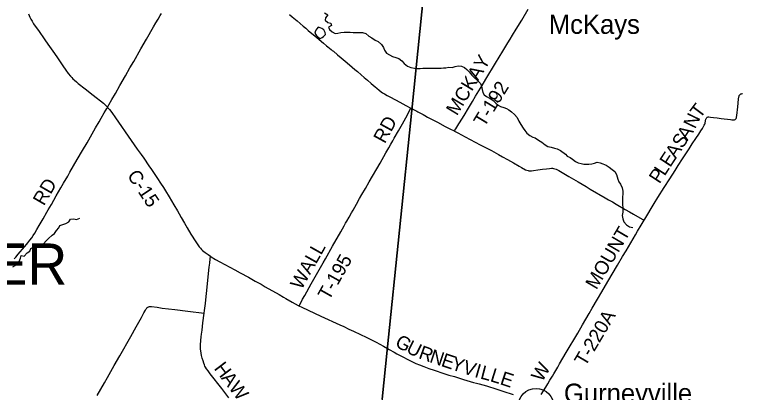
# Model space of a CAD drawing. Extents: x 1442749 to 1756758, y 235267 to 677782.
# Drawn here: x 1568709 to 1584541, y 554957 to 563182 of the extents above; entities that cross this region are included whole.
import ezdxf

# ---------------------------------------------------------------- set-up
doc = ezdxf.new("R2010")
doc.units = 0
for name, color, linetype in [('GM_X_County_Road', 7, 'Continuous'), ('GM_X_County_Road_Text', 7, 'Continuous'), ('GM_X_Minor_Lake', 7, 'Continuous'), ('GM_X_Minor_River', 7, 'Continuous'), ('GM_X_Township', 7, 'Continuous'), ('GM_X_Township_Road', 7, 'Continuous'), ('GM_X_Township_Road_Text', 7, 'Continuous'), ('GM_X_Township_Text', 7, 'Continuous'), ('GM_X_Unincorporated', 7, 'Continuous'), ('GM_X_Unincorporated_Text', 7, 'Continuous')]:
    doc.layers.add(name, color=color, linetype=linetype)

msp = doc.modelspace()

# ---------------------------------------------------------------- linework, layer by layer
at = {"layer": 'GM_X_County_Road'}
for points in [[(1569012, 563200), (1569044, 563125), (1569065, 563081), (1569090, 563035), (1569124, 562983), (1569159, 562932), (1569228, 562836), (1569370, 562631), (1569436, 562537), (1569505, 562437), (1569575, 562334), (1569640, 562240), (1569698, 562156), (1569761, 562064), (1569825, 561973), (1569878, 561902), (1569925, 561843), (1569952, 561811), (1569977, 561784), (1570010, 561753), (1570054, 561714), (1570092, 561683), (1570242, 561567), (1570418, 561430), (1570641, 561250), (1570678, 561218), (1570709, 561188), (1570733, 561162)], [(1570733, 561162), (1570761, 561214), (1570828, 561334), (1570903, 561465), (1571001, 561636), (1571122, 561850), (1571219, 562021), (1571301, 562163), (1571457, 562433), (1571579, 562643), (1571734, 562913), (1571784, 563002), (1571831, 563085), (1571878, 563164), (1571904, 563205)], [(1568701, 557862), (1568738, 557903), (1568790, 557967), (1568830, 558015), (1568934, 558137), (1568996, 558210), (1569045, 558271), (1569084, 558323), (1569117, 558372), (1569150, 558425), (1569194, 558501), (1569244, 558589), (1569330, 558737), (1569413, 558882), (1569443, 558933), (1569510, 559050), (1569618, 559237), (1569717, 559411), (1569777, 559513), (1569866, 559666), (1569914, 559748), (1570074, 560027), (1570188, 560226), (1570286, 560393), (1570472, 560714), (1570548, 560845), (1570596, 560930), (1570660, 561041), (1570695, 561101), (1570715, 561134), (1570728, 561154), (1570733, 561162)], [(1570733, 561162), (1570740, 561154), (1570771, 561116), (1570823, 561048), (1570907, 560931), (1571245, 560442), (1571378, 560255), (1571461, 560137), (1571519, 560053), (1571633, 559889), (1571687, 559810), (1571758, 559704), (1571818, 559614), (1571886, 559513), (1571951, 559415), (1571993, 559348), (1572074, 559216), (1572175, 559044), (1572253, 558911), (1572290, 558845), (1572334, 558768), (1572405, 558642), (1572462, 558543), (1572547, 558403), (1572652, 558236), (1572697, 558168), (1572726, 558128), (1572752, 558095), (1572773, 558070), (1572796, 558047), (1572823, 558024), (1572854, 558000), (1572919, 557956), (1572974, 557921)], [(1572974, 557921), (1572988, 557912), (1573083, 557854), (1573175, 557802), (1573286, 557740), (1573497, 557627), (1573615, 557562), (1573797, 557463), (1573946, 557381), (1574070, 557312), (1574163, 557258), (1574305, 557176), (1574396, 557124), (1574462, 557087), (1574562, 557031), (1574613, 557001), (1574748, 556920), (1574811, 556884), (1574877, 556849), (1574896, 556839)], [(1574896, 556839), (1574957, 556810), (1575374, 556618), (1575785, 556429), (1575871, 556389), (1575981, 556337), (1576080, 556292), (1576235, 556222), (1576356, 556163), (1576476, 556102), (1576572, 556050), (1576733, 555962), (1576860, 555892)], [(1576860, 555892), (1576966, 555834), (1577027, 555801)], [(1577027, 555801), (1577153, 555733), (1577261, 555677), (1577366, 555624), (1577437, 555590), (1577519, 555555), (1577613, 555519), (1577718, 555481), (1577833, 555442), (1578048, 555373), (1578158, 555337), (1578277, 555301), (1578474, 555239), (1578621, 555193), (1578690, 555173), (1578754, 555157), (1578817, 555142), (1578891, 555125), (1578977, 555103), (1579043, 555083), (1579137, 555054), (1579333, 554988), (1579554, 554914)]]:
    msp.add_lwpolyline(points, dxfattribs=at)
at = {"layer": 'GM_X_Minor_Lake'}
for points in [[(1575264, 562839), (1575254, 562826), (1575237, 562780), (1575271, 562734), (1575316, 562688), (1575359, 562662), (1575402, 562683), (1575430, 562706)], [(1575430, 562706), (1575473, 562748), (1575464, 562794), (1575439, 562846), (1575396, 562879), (1575354, 562896), (1575310, 562907), (1575285, 562868), (1575264, 562839)]]:
    msp.add_lwpolyline(points, dxfattribs=at)
at = {"layer": 'GM_X_Minor_River'}
for points in [[(1575453, 563219), (1575520, 563176), (1575473, 563112), (1575464, 563061), (1575521, 563011), (1575589, 562994), (1575600, 562942), (1575541, 562905), (1575562, 562854), (1575621, 562805), (1575686, 562773), (1575739, 562780), (1575809, 562791), (1575879, 562796), (1575950, 562800), (1576012, 562797), (1576072, 562792), (1576148, 562792), (1576222, 562791), (1576280, 562794), (1576350, 562766), (1576415, 562713), (1576478, 562673), (1576551, 562626), (1576617, 562594), (1576692, 562529), (1576737, 562466), (1576754, 562409), (1576798, 562342), (1576864, 562303), (1576933, 562267), (1576999, 562250), (1577065, 562229), (1577132, 562171), (1577181, 562116), (1577258, 562060), (1577332, 562033), (1577405, 562017), (1577467, 562006), (1577533, 562007), (1577592, 562012), (1577650, 562014), (1577700, 562015), (1577754, 562014), (1577810, 562013), (1577874, 562016), (1577925, 562015), (1577989, 562016), (1578039, 562019), (1578089, 562024), (1578154, 562037), (1578224, 562033), (1578292, 562050), (1578359, 562065), (1578431, 562061), (1578494, 562028), (1578549, 561983), (1578594, 561932), (1578653, 561860), (1578712, 561801), (1578781, 561745), (1578844, 561678), (1578867, 561625), (1578878, 561551), (1578892, 561484), (1578921, 561434), (1578973, 561397), (1579052, 561353), (1579117, 561310), (1579174, 561252), (1579226, 561209), (1579277, 561184), (1579353, 561159), (1579407, 561139), (1579458, 561108), (1579521, 561065), (1579584, 561008), (1579643, 560938), (1579680, 560859), (1579722, 560788), (1579769, 560711), (1579810, 560658)], [(1579227, 561268), (1579151, 561326), (1579152, 561325)], [(1579810, 560658), (1579853, 560597), (1579916, 560550), (1579984, 560516), (1580035, 560497), (1580107, 560450), (1580176, 560402), (1580247, 560343), (1580310, 560311), (1580380, 560296), (1580452, 560277), (1580508, 560257), (1580585, 560224), (1580689, 560141)], [(1580689, 560141), (1580727, 560097), (1580793, 560069), (1580845, 560037), (1580908, 559981), (1580970, 559958), (1581035, 559939), (1581091, 559928), (1581143, 559926), (1581203, 559925), (1581262, 559930), (1581324, 559945), (1581380, 559966), (1581450, 559957), (1581502, 559936), (1581576, 559907), (1581639, 559863), (1581710, 559810), (1581764, 559763), (1581801, 559703), (1581814, 559652), (1581829, 559596), (1581852, 559539), (1581891, 559489), (1581924, 559414), (1581943, 559337), (1581940, 559281), (1581930, 559207), (1581932, 559157), (1581930, 559093), (1581932, 559039), (1581937, 558983), (1581940, 558932), (1581939, 558880), (1581926, 558812), (1581942, 558734), (1581963, 558667), (1582016, 558606), (1582088, 558563), (1582155, 558546)], [(1568669, 557690), (1568724, 557717), (1568755, 557785), (1568808, 557810), (1568839, 557877), (1568850, 557935), (1568918, 557924), (1568982, 557993), (1569045, 558032), (1569062, 558087), (1569127, 558128), (1569193, 558145), (1569266, 558165), (1569337, 558194), (1569396, 558257), (1569449, 558308), (1569525, 558377), (1569576, 558414), (1569621, 558481), (1569670, 558538), (1569697, 558594), (1569758, 558613), (1569827, 558631), (1569889, 558672), (1569929, 558728), (1570001, 558736), (1570057, 558723), (1570128, 558748)]]:
    msp.add_lwpolyline(points, dxfattribs=at)
at = {"layer": 'GM_X_Township'}
for points in [[(1567480, 573618), (1572928, 573040), (1578513, 572449), (1578438, 571717), (1577745, 564960), (1577349, 561102), (1576814, 555881), (1576704, 554811), (1576386, 550844), (1576369, 550638), (1576189, 548397), (1576129, 547648), (1575922, 544864), (1575631, 540931), (1575571, 540239), (1575500, 539411), (1574568, 539459), (1566007, 539894)], [(1576704, 554811), (1576814, 555881), (1577349, 561102), (1577745, 564960), (1578438, 571717), (1578513, 572449), (1579838, 572308), (1580857, 572200), (1588468, 571492), (1591507, 571209), (1594558, 570925), (1600110, 570408), (1601218, 570299), (1605315, 569892), (1608125, 569657), (1616080, 568853), (1618534, 568633), (1622375, 568282), (1623453, 568184), (1622446, 566839), (1615321, 557320), (1613178, 554457)]]:
    msp.add_lwpolyline(points, dxfattribs=at)
at = {"layer": 'GM_X_Township_Road'}
for points in [[(1578277, 560645), (1578288, 560663), (1578306, 560692), (1578375, 560804), (1578450, 560928), (1578508, 561023), (1578559, 561107), (1578668, 561290), (1578738, 561405), (1578807, 561520), (1578878, 561638), (1578962, 561776), (1579170, 562121), (1579332, 562388), (1579441, 562567), (1579487, 562643), (1579539, 562730), (1579621, 562865), (1579741, 563061), (1579884, 563300)], [(1574688, 563185), (1574750, 563132), (1574855, 563043), (1574922, 562985), (1574985, 562932), (1575044, 562882), (1575099, 562835), (1575212, 562741), (1575275, 562689), (1575382, 562597), (1575430, 562557), (1575495, 562502), (1575523, 562479), (1575597, 562419), (1575620, 562400), (1575643, 562382), (1575733, 562305), (1575810, 562240), (1575941, 562130), (1576055, 562036), (1576110, 561989), (1576165, 561943), (1576250, 561871), (1576314, 561815), (1576384, 561755), (1576469, 561683), (1576550, 561612), (1576588, 561580), (1576639, 561538), (1576685, 561502), (1576715, 561481), (1576757, 561455), (1576817, 561421), (1576886, 561383), (1577087, 561278), (1577223, 561206), (1577330, 561148)], [(1582401, 558705), (1582416, 558729), (1582618, 559070), (1582698, 559202), (1582837, 559421), (1582959, 559607), (1583079, 559791), (1583146, 559896), (1583241, 560042), (1583337, 560191), (1583382, 560259), (1583451, 560367), (1583526, 560483), (1583591, 560581), (1583638, 560652), (1583669, 560699), (1583697, 560743), (1583712, 560773), (1583722, 560798), (1583728, 560820), (1583739, 560869), (1583748, 560905), (1583752, 560919), (1583757, 560930), (1583764, 560939), (1583772, 560945), (1583779, 560950), (1583784, 560952), (1583793, 560953), (1583809, 560954), (1583845, 560951), (1583910, 560944), (1583991, 560934), (1584079, 560922), (1584278, 560895), (1584307, 560891), (1584323, 560890), (1584337, 560890), (1584357, 560891), (1584370, 560894), (1584380, 560898), (1584389, 560904), (1584397, 560911), (1584405, 560923), (1584409, 560933), (1584413, 560949), (1584419, 560985), (1584439, 561175), (1584455, 561342), (1584457, 561361), (1584460, 561377), (1584463, 561393), (1584467, 561408), (1584471, 561420), (1584477, 561431), (1584484, 561440), (1584489, 561444), (1584497, 561449), (1584504, 561454), (1584513, 561457), (1584522, 561459), (1584532, 561461), (1584544, 561462)], [(1574896, 556839), (1574904, 556855), (1574940, 556923), (1574974, 556987), (1575020, 557070), (1575161, 557319), (1575276, 557521), (1575364, 557675), (1575422, 557778), (1575470, 557864), (1575622, 558140), (1575803, 558456), (1575877, 558587), (1575910, 558644), (1575935, 558686), (1575986, 558774), (1576038, 558865), (1576072, 558925), (1576144, 559057), (1576213, 559176), (1576264, 559265), (1576339, 559396), (1576423, 559544), (1576658, 559950), (1576784, 560169), (1576850, 560283), (1576896, 560362), (1576935, 560434), (1576967, 560491), (1577058, 560651), (1577144, 560805), (1577218, 560934), (1577272, 561031), (1577324, 561136), (1577330, 561148)], [(1577330, 561148), (1577384, 561118), (1577459, 561078), (1577483, 561065)], [(1577483, 561065), (1577539, 561033), (1577594, 561003), (1577632, 560983), (1577693, 560952), (1577908, 560839), (1578076, 560749), (1578177, 560695), (1578268, 560650), (1578277, 560645)], [(1578277, 560645), (1578353, 560606), (1578512, 560522), (1578840, 560349), (1578993, 560267), (1579080, 560221), (1579232, 560137), (1579320, 560086), (1579429, 560025), (1579564, 559952), (1579688, 559883), (1579735, 559854), (1579825, 559805), (1579852, 559793), (1579879, 559786), (1579895, 559784), (1579922, 559783), (1579955, 559784), (1579995, 559788), (1580092, 559803), (1580193, 559816), (1580277, 559826), (1580343, 559832), (1580391, 559836), (1580410, 559835), (1580433, 559832), (1580461, 559826), (1580489, 559817), (1580515, 559805), (1580544, 559790), (1580620, 559745), (1580763, 559658), (1580966, 559538), (1581139, 559436), (1581227, 559385), (1581557, 559196), (1581631, 559153), (1581713, 559106), (1581798, 559057), (1581993, 558941), (1582086, 558886), (1582174, 558835), (1582362, 558727), (1582401, 558705)], [(1580166, 554911), (1580217, 554995), (1580262, 555071), (1580306, 555144), (1580354, 555222), (1580408, 555314), (1580437, 555364), (1580524, 555511), (1580564, 555582), (1580708, 555828), (1580958, 556248), (1581064, 556430), (1581210, 556678), (1581274, 556789), (1581389, 556984), (1581483, 557146), (1581614, 557370), (1581823, 557726), (1581935, 557915), (1582010, 558043), (1582214, 558391), (1582259, 558467), (1582337, 558596), (1582401, 558705)], [(1572834, 556683), (1572842, 556740), (1572859, 556890), (1572868, 556975), (1572882, 557109), (1572944, 557686), (1572954, 557774), (1572966, 557862), (1572974, 557921)], [(1570508, 554894), (1570663, 555168), (1570731, 555285), (1570879, 555547), (1570996, 555756), (1571235, 556175), (1571352, 556387), (1571468, 556592), (1571520, 556687), (1571555, 556750), (1571573, 556776), (1571585, 556792), (1571596, 556804), (1571609, 556813), (1571623, 556820), (1571632, 556823), (1571648, 556826), (1571664, 556827), (1571686, 556826), (1571810, 556810), (1571920, 556795), (1572194, 556761), (1572477, 556726), (1572834, 556683)], [(1573371, 554842), (1573217, 555042), (1572965, 555366), (1572920, 555426), (1572886, 555474), (1572865, 555507), (1572851, 555532), (1572840, 555556), (1572825, 555592), (1572809, 555642), (1572792, 555702), (1572776, 555762), (1572767, 555810), (1572760, 555865), (1572756, 555901), (1572755, 555949), (1572755, 555970), (1572756, 555992), (1572764, 556087), (1572771, 556165), (1572777, 556226), (1572787, 556314), (1572806, 556470), (1572834, 556683)]]:
    msp.add_lwpolyline(points, dxfattribs=at)
at = {"layer": 'GM_X_Unincorporated'}
msp.add_circle((1580051, 554649), 393, dxfattribs=at)

# ---------------------------------------------------------------- texts
at = {"layer": 'GM_X_County_Road_Text'}
for s, rotation, p in [('C-15', 303.6894, (1571147, 559680)), ('RD', 59.8856, (1569349, 559003)), ('G', 330.9718, (1576964, 555974)), ('U', 333.453, (1577207, 555840)), ('R', 340.2225, (1577479, 555706)), ('N', 341.5914, (1577718, 555621)), ('E', 341.6005, (1577969, 555537)), ('Y', 341.6068, (1578182, 555466)), ('V', 342.1055, (1578435, 555382)), ('I', 343.9915, (1578697, 555298)), ('L', 345.4927, (1578823, 555262)), ('L', 342.8059, (1579037, 555206)), ('E', 341.7805, (1579250, 555140))]:
    msp.add_text(s, height=300, rotation=rotation, dxfattribs=at).set_placement(p)
at = {"layer": 'GM_X_Township_Road_Text'}
for s, rotation, p in [('MCKAY', 58.7254, (1578331, 560964)), ('T-192', 58.7039, (1578929, 560715)), ('T', 52.9775, (1583618, 560902)), ('RD', 61.2338, (1576760, 560358)), ('N', 64.2583, (1583511, 560678)), ('A', 56.936, (1583346, 560420)), ('S', 56.929, (1583236, 560250)), ('A', 56.9273, (1583092, 560029)), ('E', 56.9281, (1582969, 559841)), ('P', 56.9319, (1582737, 559483)), ('L', 56.928, (1582847, 559653)), ('MOUNT', 59.5154, (1581365, 557177)), ('WALL', 60.5762, (1574949, 557175)), ('T-195', 60.6738, (1575550, 556942)), ('T-220A', 59.403, (1581124, 555506)), ('H', 307.2371, (1573034, 555478)), ('W', 59.1476, (1580183, 555168)), ('A', 307.2357, (1573193, 555268)), ('W', 307.2329, (1573353, 555058))]:
    msp.add_text(s, height=300, rotation=rotation, dxfattribs=at).set_placement(p)
at = {"layer": 'GM_X_Township_Text'}
msp.add_text('CHESTER', height=900, rotation=0, dxfattribs=at).set_placement((1564107, 557300))
at = {"layer": 'GM_X_Unincorporated_Text'}
for s, p in [('McKays', (1580328, 562762)), ('Gurneyville', (1580658, 554732))]:
    msp.add_text(s, height=417, rotation=0, dxfattribs=at).set_placement(p)

doc.saveas('drawing.dxf')
